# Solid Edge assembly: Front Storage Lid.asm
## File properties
Author: m_hel
Template: Iso Metric Assembly.asm
Last saved by: m_hel
Revision: 8
Application: Solid Edge
Username: m_hel
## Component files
Front Storage Lid 2.par
Lid Handle.asm
Lid Hinge.asm
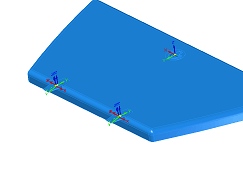
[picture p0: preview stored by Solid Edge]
